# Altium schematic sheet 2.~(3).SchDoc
size 420 x 297 mm
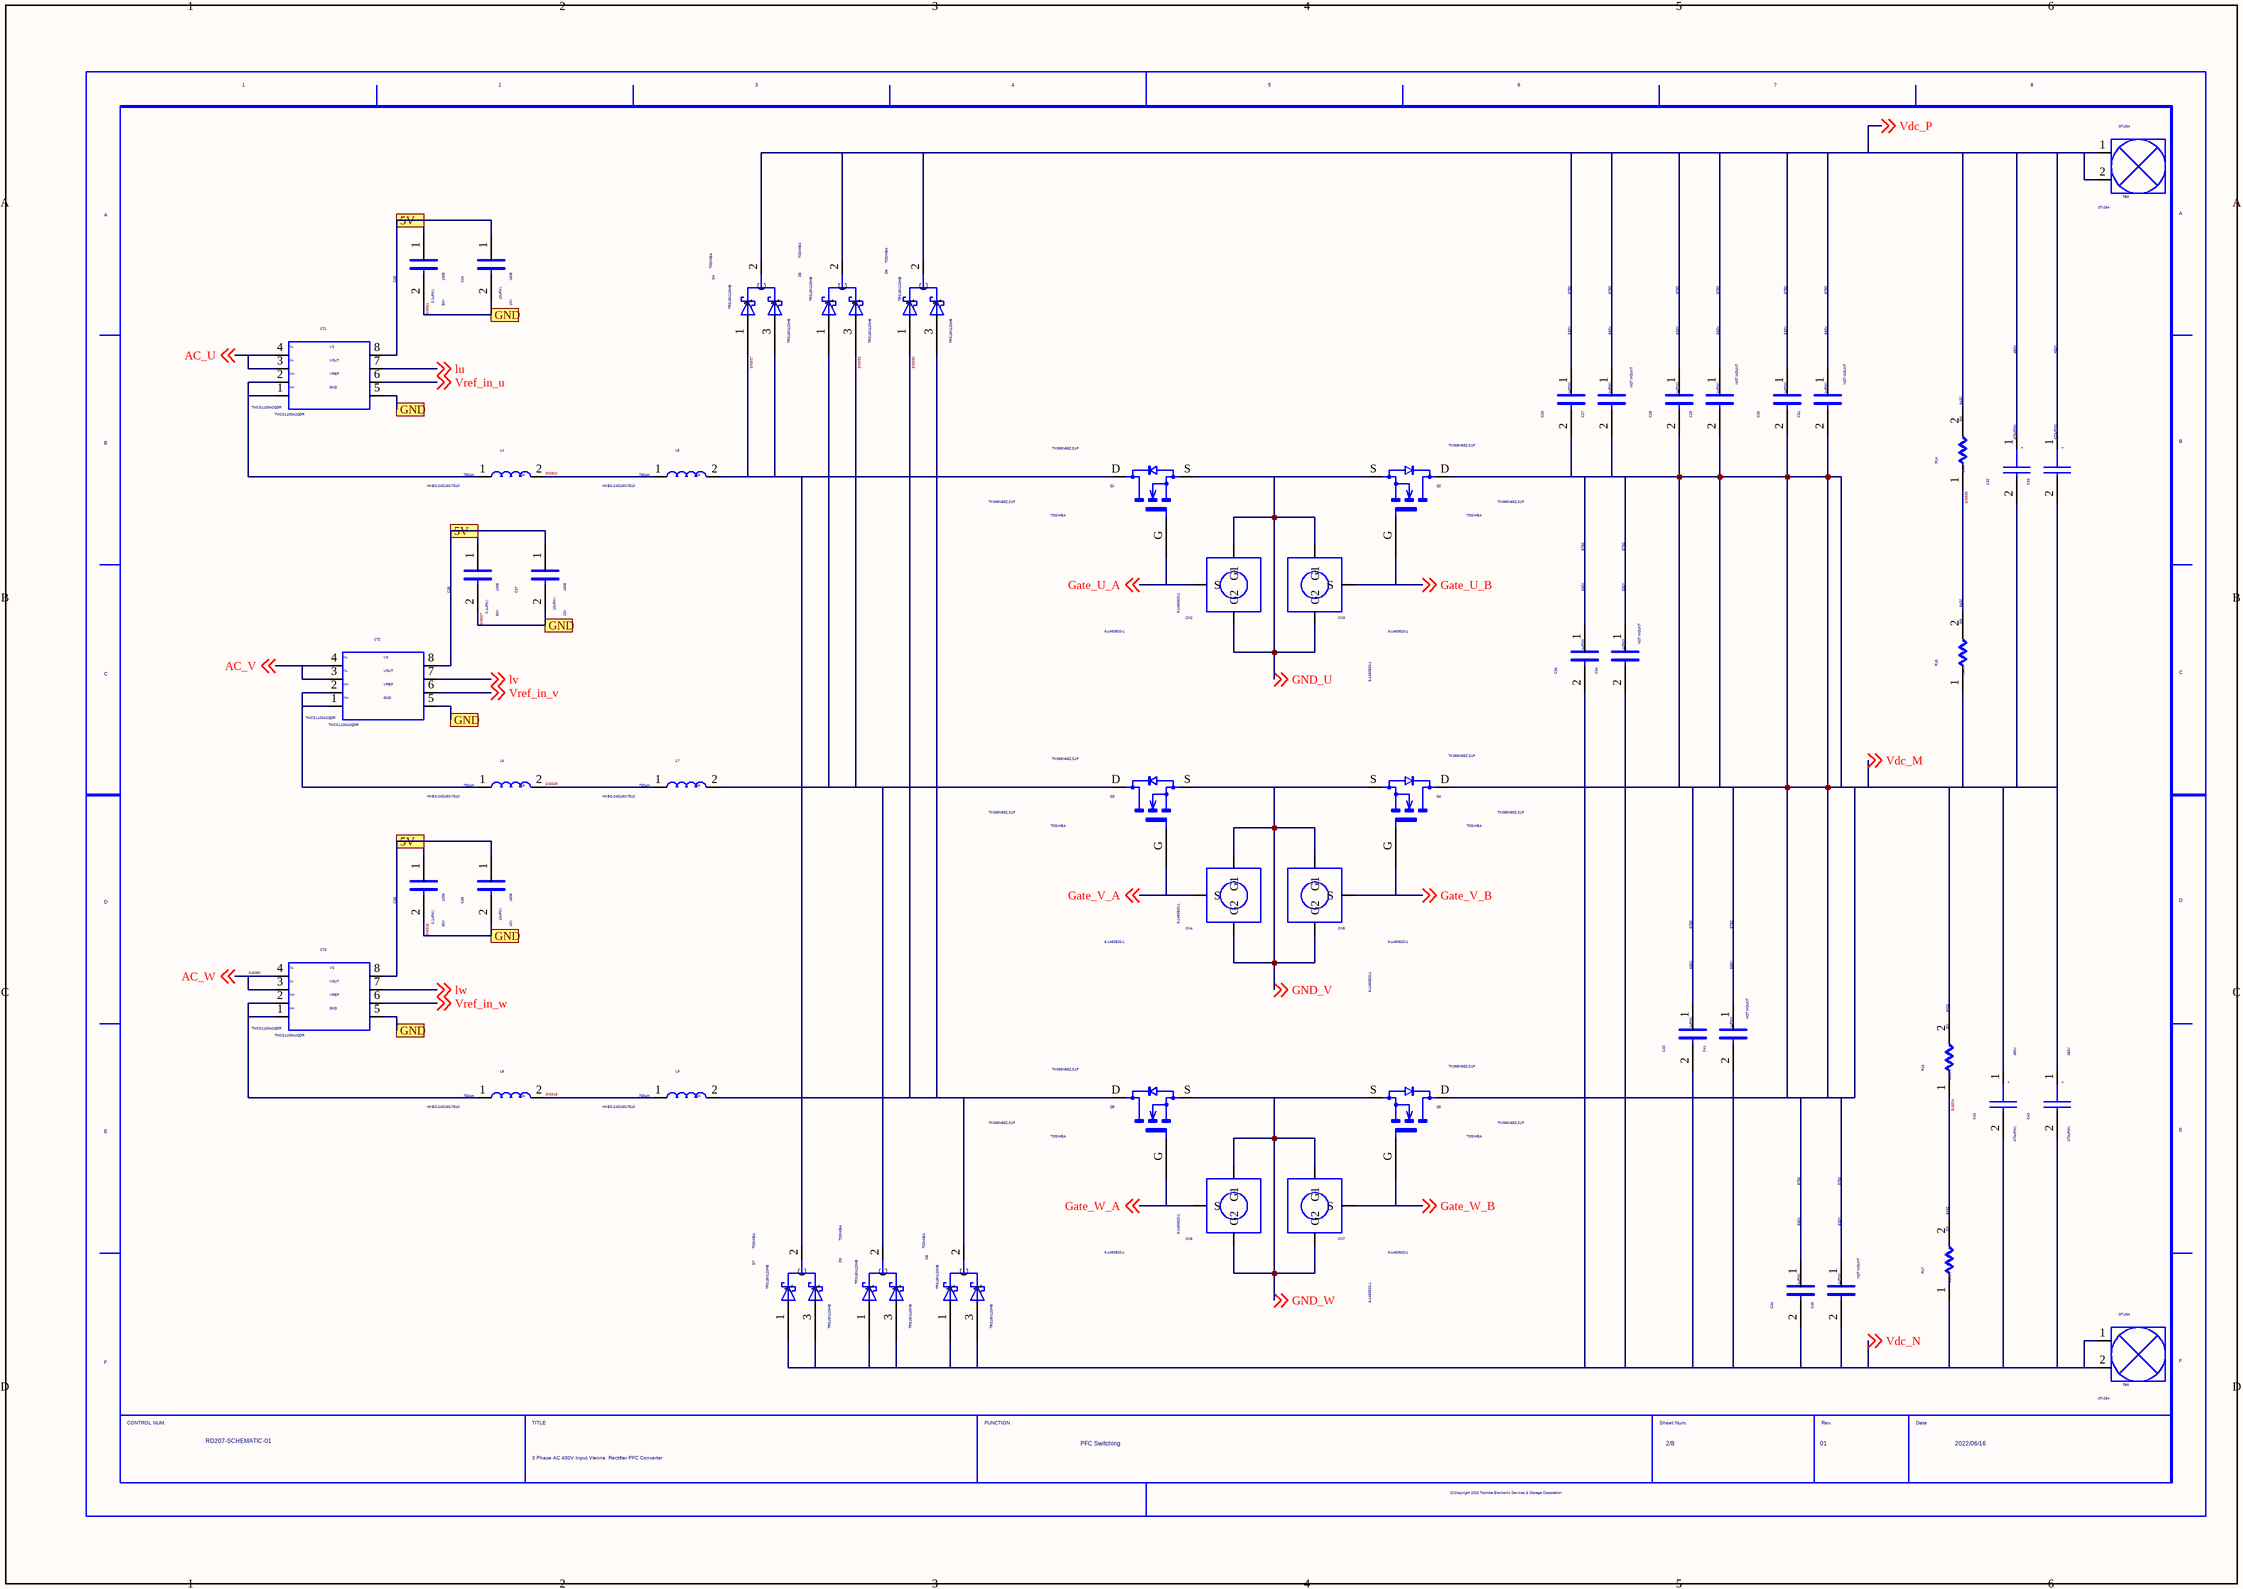
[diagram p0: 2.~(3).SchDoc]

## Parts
C24  SIZECODESMD: 1608  VAL2: 10V  VAL1: 10uF(K)  (hidden comment: C)
C25  SIZECODESMD: 1005  VAL2: 50V  VAL1: 0.1uF(K)  (hidden comment: C)
C26  SIZECODESMD: 5750  VAL2: 630V  VAL1: 1uF(M)  (hidden comment: C)
C27  NOTMOUNT: NOT MOUNT  SIZECODESMD: 5750  VAL2: 630V  VAL1: 1uF(M)  (hidden comment: C)
C28  SIZECODESMD: 5750  VAL2: 630V  VAL1: 1uF(M)  (hidden comment: C)
C29  NOTMOUNT: NOT MOUNT  SIZECODESMD: 5750  VAL2: 630V  VAL1: 1uF(M)  (hidden comment: C)
C30  SIZECODESMD: 5750  VAL2: 630V  VAL1: 1uF(M)  (hidden comment: C)
C31  NOTMOUNT: NOT MOUNT  SIZECODESMD: 5750  VAL2: 630V  VAL1: 1uF(M)  (hidden comment: C)
C32  VAL2: 450V  VAL1: 470uF(M)  (hidden comment: CP)
C33  VAL2: 450V  VAL1: 470uF(M)  (hidden comment: CP)
C34  NOTMOUNT: NOT MOUNT  SIZECODESMD: 5750  VAL2: 630V  VAL1: 1uF(M)  (hidden comment: C)
C35  SIZECODESMD: 1005  VAL2: 50V  VAL1: 0.1uF(K)  (hidden comment: C)
C36  SIZECODESMD: 5750  VAL2: 630V  VAL1: 1uF(M)  (hidden comment: C)
C37  SIZECODESMD: 1608  VAL2: 10V  VAL1: 10uF(K)  (hidden comment: C)
C38  SIZECODESMD: 1608  VAL2: 10V  VAL1: 10uF(K)  (hidden comment: C)
C39  SIZECODESMD: 1005  VAL2: 50V  VAL1: 0.1uF(K)  (hidden comment: C)
C40  SIZECODESMD: 5750  VAL2: 630V  VAL1: 1uF(M)  (hidden comment: C)
C41  NOTMOUNT: NOT MOUNT  SIZECODESMD: 5750  VAL2: 630V  VAL1: 1uF(M)  (hidden comment: C)
C42  VAL2: 450V  VAL1: 470uF(M)  (hidden comment: CP)
C43  VAL2: 450V  VAL1: 470uF(M)  (hidden comment: CP)
C44  SIZECODESMD: 5750  VAL2: 630V  VAL1: 1uF(M)  (hidden comment: C)
C45  NOTMOUNT: NOT MOUNT  SIZECODESMD: 5750  VAL2: 630V  VAL1: 1uF(M)  (hidden comment: C)
CN2  6-1460820-1
CN3  6-1460820-1
CN4  6-1460820-1
CN5  6-1460820-1
CN6  6-1460820-1
CN7  6-1460820-1
CT1  TMCS1100A2QDR
CT2  TMCS1100A2QDR
CT3  TMCS1100A2QDR
D4  TRS15N120HB  USERCOMPTEXT3: TOSHIBA
D5  TRS15N120HB  USERCOMPTEXT3: TOSHIBA
D6  TRS15N120HB  USERCOMPTEXT3: TOSHIBA
D7  TRS15N120HB  USERCOMPTEXT3: TOSHIBA
D8  TRS15N120HB  USERCOMPTEXT3: TOSHIBA
D9  TRS15N120HB  USERCOMPTEXT3: TOSHIBA
L4  VAL3: HKBS-24D160-7510  VAL2: 10A  VAL1: 750uH  (hidden comment: L)
L5  VAL3: HKBS-24D160-7510  VAL2: 10A  VAL1: 750uH  (hidden comment: L)
L6  VAL3: HKBS-24D160-7510  VAL2: 10A  VAL1: 750uH  (hidden comment: L)
L7  VAL3: HKBS-24D160-7510  VAL2: 10A  VAL1: 750uH  (hidden comment: L)
L8  VAL3: HKBS-24D160-7510  VAL2: 10A  VAL1: 750uH  (hidden comment: L)
L9  VAL3: HKBS-24D160-7510  VAL2: 10A  VAL1: 750uH  (hidden comment: L)
Q1  TK065N65Z,S1F  USERCOMPTEXT3: TOSHIBA
Q2  TK065N65Z,S1F  USERCOMPTEXT3: TOSHIBA
Q3  TK065N65Z,S1F  USERCOMPTEXT3: TOSHIBA
Q4  TK065N65Z,S1F  USERCOMPTEXT3: TOSHIBA
Q5  TK065N65Z,S1F  USERCOMPTEXT3: TOSHIBA
Q6  TK065N65Z,S1F  USERCOMPTEXT3: TOSHIBA
R14  SIZECODESMD: 6432  VAL2: 3W  VAL1: 39k(F)  (hidden comment: R)
R15  SIZECODESMD: 6432  VAL2: 3W  VAL1: 39k(F)  (hidden comment: R)
R16  SIZECODESMD: 6432  VAL2: 3W  VAL1: 39k(F)  (hidden comment: R)
R17  SIZECODESMD: 6432  VAL2: 3W  VAL1: 39k(F)  (hidden comment: R)
TB5  OT-264
TB6  OT-264
U?  DATE: 2022/06/16  TITLE: 3 Phase AC 400V Input Vienna / Rectifier PFC Converter  DRAWINGNUMBER: RD207-SCHEMATIC-01  REVISION: 01  SHEETNUMBER: 2/8  FUNCTION: PFC Switching  (hidden comment: WAKU_DEF100)

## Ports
5V, GND

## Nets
AC_U: CT1.3 CT1.4 ; off-sheet AC_U
AC_V: CT2.3 CT2.4 ; off-sheet AC_V
Gate_U_A: CN2.S Q1.G ; off-sheet Gate_U_A
Gate_U_B: CN3.S Q2.G ; off-sheet Gate_U_B
Gate_V_A: CN4.S Q3.G ; off-sheet Gate_V_A
Gate_V_B: CN5.S Q4.G ; off-sheet Gate_V_B
Gate_W_A: CN6.S Q5.G ; off-sheet Gate_W_A
Gate_W_B: CN7.S Q6.G ; off-sheet Gate_W_B
GND_U: CN2.G1 CN2.G2 CN3.G1 CN3.G2 Q1.S Q2.S ; off-sheet GND_U
GND_V: CN4.G1 CN4.G2 CN5.G1 CN5.G2 Q3.S Q4.S ; off-sheet GND_V
GND_W: CN6.G1 CN6.G2 CN7.G1 CN7.G2 Q5.S Q6.S ; off-sheet GND_W
lu: CT1.7 ; off-sheet lu
lv: CT2.7 ; off-sheet lv
lw: CT3.7 ; off-sheet lw
SIG314: C24.1 C25.1 C35.1 C37.1 C38.1 C39.1 CT1.8 CT2.8 CT3.8 ; port 5V  [also labelled SIG328]
SIG315: C24.2 C25.2 C35.2 C37.2 C38.2 C39.2 CT1.5 CT2.5 CT3.5 ; port GND  [also labelled SIG321, SIG327]
SIG317: CT3.1 CT3.2 L8.1
SIG318: L8.2 L9.1
SIG322: L4.2 L5.1
SIG325: CT1.1 CT1.2 L4.1
SIG329: L6.2 L7.1
SIG330: CT2.1 CT2.2 L6.1
SIG332: D6.1(A) D6.3(A) D8.2(C) L9.2 Q5.D
SIG333: D5.1(A) D5.3(A) D9.2(C) L7.2 Q3.D
SIG334: R16.1 R17.2
SIG335: R14.1 R15.2
SIG337: D4.1(A) D4.3(A) D7.2(C) L5.2 Q1.D
SIG360: CT3.3 CT3.4 ; off-sheet AC_W  [also labelled AC_W]
Vdc_M: C26.2 C27.2 C28.2 C29.2 C30.2 C31.2 C32.2 C33.2 C34.1 C36.1 C40.1 C41.1 C42.1 C43.1 C44.1 C45.1 Q2.D Q4.D Q6.D R15.1 R16.2 ; off-sheet Vdc_M
Vdc_N: C34.2 C36.2 C40.2 C41.2 C42.2 C43.2 C44.2 C45.2 D7.1(A) D7.3(A) D8.1(A) D8.3(A) D9.1(A) D9.3(A) R17.1 TB6.1 TB6.2 ; off-sheet Vdc_N
Vdc_P: C26.1 C27.1 C28.1 C29.1 C30.1 C31.1 C32.1 C33.1 D4.2(C) D5.2(C) D6.2(C) R14.2 TB5.1 TB5.2 ; off-sheet Vdc_P
Vref_in_u: CT1.6 ; off-sheet Vref_in_u
Vref_in_v: CT2.6 ; off-sheet Vref_in_v
Vref_in_w: CT3.6 ; off-sheet Vref_in_w

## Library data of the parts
C24 C37 C38 = C: OriginalSymbolOrigin: (2540,7620); COMP: -C-GRM188D71A106KA73D
C25 C35 C39 = C: OriginalSymbolOrigin: (2540,7620); COMP: -C-UMK105BJ104KV-F
C26 C28 C30 C36 C40 C44 = C: OriginalSymbolOrigin: (2540,7620); COMP: -C-CAA572X7T2J105M640LH
C27 C29 C31 C34 C41 C45 = C: OriginalSymbolOrigin: (2540,7620); COMP: -C-NC_CAA572X7T2J105M640LH
C32 C33 C42 C43 = CP: SAVEAREA0: -1450,-153,20294,13055; SAVECOUNT: 52; TIME: 15:02:55; UPDATEUSER: fukuda-y; UPDATETIME: 16:13:42; OriginalSymbolOrigin: (2540,10160); COMP: -C-450MXK470MEFCSN25X55
CN2-CN7 = 6_1460820_1: MMCX Connector, 170V; MANUFACTURER: TE Connectivity; COMP: CN-6-1460820-1_Micro_SP-NoTH; TIME: 11:39:41; UPDATEUSER: t5459927; UPDATETIME: 13:55:13; SAVECOUNT: 2; SAVEAREA0: -9060,-19760,18940,737; OriginalSymbolOrigin: (0,0)
CT1-CT3 = TMCS1100A2QDR: COMP: -CT-TMCS1100A2QDR; TIME: 11:39:42; UPDATEUSER: t5459927; UPDATETIME: 14:02:58; SAVECOUNT: 5; SAVEAREA0: -9737,-18768,24721,6457; OriginalSymbolOrigin: (0,0)
D4 = TRS15N120HB: SiC Schottky Barrier Diode Array; COMP: D-TRS15N120HB; NOTE: 1200V; TIME: 11:39:42; UPDATEUSER: t5459927; SAVECOUNT: 1; OriginalSymbolOrigin: (0,0); INSTANCENAME: INS17355299
D5 = TRS15N120HB: SiC Schottky Barrier Diode Array; COMP: D-TRS15N120HB; NOTE: 1200V; TIME: 11:39:42; UPDATEUSER: t5459927; SAVECOUNT: 1; OriginalSymbolOrigin: (0,0); INSTANCENAME: INS17355445
D6 = TRS15N120HB: SiC Schottky Barrier Diode Array; COMP: D-TRS15N120HB; NOTE: 1200V; TIME: 11:39:42; UPDATEUSER: t5459927; SAVECOUNT: 1; OriginalSymbolOrigin: (0,0); INSTANCENAME: INS17355424
D7 = TRS15N120HB: SiC Schottky Barrier Diode Array; COMP: D-TRS15N120HB_SP; NOTE: 1200V; TIME: 11:39:42; UPDATEUSER: t5459927; SAVECOUNT: 1; OriginalSymbolOrigin: (0,0); INSTANCENAME: INS17355299
D8 = TRS15N120HB: SiC Schottky Barrier Diode Array; COMP: D-TRS15N120HB_SP; NOTE: 1200V; TIME: 11:39:42; UPDATEUSER: t5459927; SAVECOUNT: 1; OriginalSymbolOrigin: (0,0); INSTANCENAME: INS17355424
D9 = TRS15N120HB: SiC Schottky Barrier Diode Array; COMP: D-TRS15N120HB_SP; NOTE: 1200V; TIME: 11:39:42; UPDATEUSER: t5459927; SAVECOUNT: 1; OriginalSymbolOrigin: (0,0); INSTANCENAME: INS17355445
L4-L9 = L: OriginalSymbolOrigin: (2540,5080); COMP: L-HKBS-24D160-7510
Q1-Q6 = TK065N65Z_S1F: Power MOS FET; COMP: Q-TK065N65Z_TATE; NOTE: 650V 30A; TIME: 11:39:42; UPDATEUSER: t5459927; UPDATETIME: 13:16:21; SAVECOUNT: 2; SAVEAREA0: -16850,-13021,18411,3375; OriginalSymbolOrigin: (0,0)
R14-R17 = R: OriginalSymbolOrigin: (5080,5080); COMP: -R-352239KFT
TB5 TB6 = OT_264: Terminal, 50A, M4; MANUFACTURER: Osada; COMP: -TB-OT-264; TIME: 11:39:39; UPDATEUSER: t5459927; UPDATETIME: 13:18:21; SAVECOUNT: 2; SAVEAREA0: -3825,-10384,11105,546; OriginalSymbolOrigin: (0,0)
U? = WAKU_DEF100: PLOTTIME: HH:MM; SAVEAREA0: 22200,72372,612276,319236; TIME: 14:30:25; UPDATEUSER: t5459927; UPDATETIME: 09:21:32; SAVECOUNT: 7; OriginalSymbolOrigin: (10160,284480)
